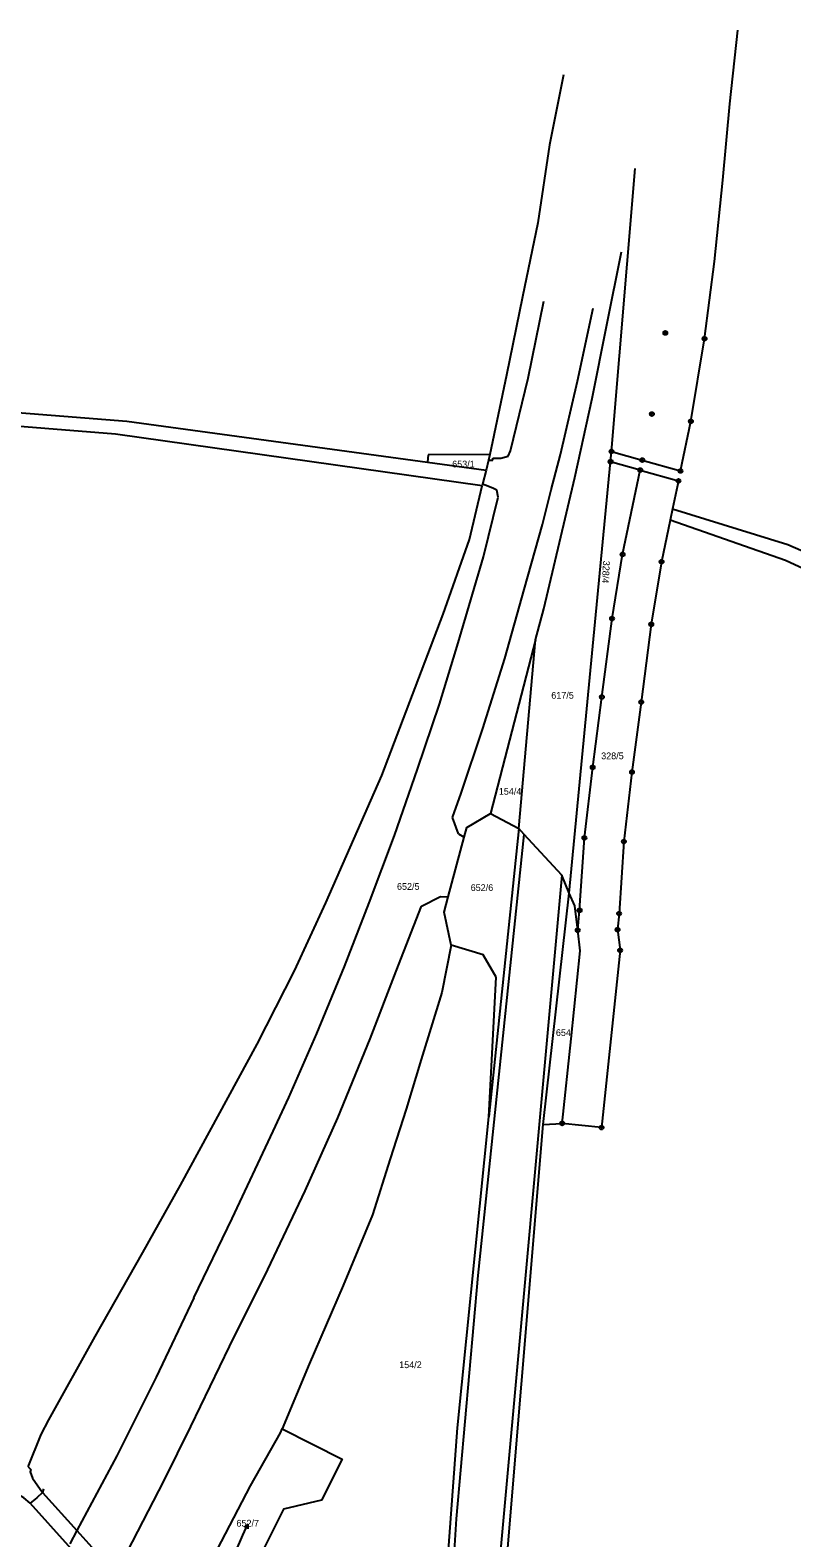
# Model space of a CAD drawing. Extents: x -783948 to -781889, y -1005870 to -1004430.
# Drawn here: x -783066.7 to -782874.5, y -1004810.4 to -1004430 of the extents above; entities that cross this region are included whole.
import ezdxf

# ---------------------------------------------------------------- set-up
doc = ezdxf.new("R2010")
doc.units = 0
for name, color, linetype in [('Vrstva 1', 7, 'Continuous'), ('Vrstva 2', 7, 'Continuous'), ('Vrstva 4', 7, 'Continuous'), ('Vrstva 7', 7, 'Continuous'), ('Vrstva 8', 7, 'Continuous')]:
    doc.layers.add(name, color=color, linetype=linetype)

msp = doc.modelspace()

# ---------------------------------------------------------------- linework, layer by layer
at = {"layer": 'Vrstva 1'}
for p, q in [((-782919.98, -1004536.27), (-782914.02, -1004464.87)), ((-782966.25, -1004537.12), (-782966.43, -1004538.99)), ((-782966.43, -1004538.99), (-782951.63, -1004541.02)), ((-782950.65, -1004537.03), (-782966.25, -1004537.12)), ((-782930.64, -1004647.72), (-782920.21, -1004538.85)), ((-782920.21, -1004538.85), (-782919.98, -1004536.27)), ((-782912.74, -1004540.96), (-782920.21, -1004538.85)), ((-782919.98, -1004536.27), (-782912.22, -1004538.46)), ((-782912.74, -1004540.96), (-782903.1, -1004543.69)), ((-782955.84, -1004558.52), (-782952.59, -1004544.91)), ((-782903.1, -1004543.69), (-782904.56, -1004550.71)), ((-782904.56, -1004550.71), (-782905.17, -1004553.62)), ((-782905.17, -1004553.62), (-782907.36, -1004564.1)), ((-782939.16, -1004583.81), (-782937.08, -1004575.97)), ((-782939.16, -1004583.81), (-782950.52, -1004627.63)), ((-782943.41, -1004631.44), (-782939.16, -1004583.81)), ((-782950.52, -1004627.63), (-782943.41, -1004631.44)), ((-782943.41, -1004631.44), (-782950.94, -1004704.2)), ((-782937.24, -1004706.12), (-782930.64, -1004647.72)), ((-782929.28, -1004650.94), (-782930.64, -1004647.72)), ((-782928.52, -1004657.08), (-782929.28, -1004650.94)), ((-782950.94, -1004704.2), (-782949.09, -1004668.94)), ((-782937.24, -1004706.12), (-782932.44, -1004705.83))]:
    msp.add_line(p, q, dxfattribs=at)
for points in [[(-782912.22, -1004538.46), (-782902.58, -1004541.19), (-782899.97, -1004528.67), (-782896.52, -1004507.82), (-782894, -1004488.33), (-782891.9, -1004467.84), (-782890.11, -1004448.58), (-782888.09, -1004429.95)], [(-782932.1, -1004441.24), (-782935.62, -1004458.85), (-782938.62, -1004478.6), (-782942.47, -1004497.23), (-782946.46, -1004517), (-782950.65, -1004537.03)], [(-782937.08, -1004575.97), (-782933.11, -1004559.26), (-782929.22, -1004542.81), (-782924.88, -1004522.91), (-782921.19, -1004504.35), (-782917.43, -1004485.86)], [(-782952.59, -1004544.91), (-783045.16, -1004531.87), (-783194.17, -1004519.95), (-783214.2, -1004520.81), (-783251.02, -1004519.09)], [(-783142, -1004520.7), (-783042.27, -1004528.59), (-782966.43, -1004538.99)], [(-782950.65, -1004537.03), (-782951.01, -1004538.49), (-782951.63, -1004541.02)], [(-782951.63, -1004541.02), (-782952.5, -1004544.55), (-782952.59, -1004544.91)], [(-782928.52, -1004657.08), (-782928.04, -1004652.07), (-782926.83, -1004633.8), (-782924.74, -1004615.97), (-782922.41, -1004598.24), (-782919.85, -1004578.44), (-782917.19, -1004562.27), (-782912.74, -1004540.96)], [(-782904.56, -1004550.71), (-782875.46, -1004559.76), (-782809.9, -1004588.39)], [(-782430.34, -1004673.42), (-782440.81, -1004671.9), (-782506.88, -1004656.53), (-782532.47, -1004648.66), (-782552.87, -1004641.62), (-782611, -1004618.35), (-782660.1, -1004608.13), (-782699.65, -1004606.49), (-782716.76, -1004604.99), (-782744.66, -1004601.77), (-782777.18, -1004599.46), (-782781.14, -1004603.06), (-782803.24, -1004595.16), (-782813.97, -1004592.59), (-782876.12, -1004563.82), (-782905.17, -1004553.62)], [(-783067.21, -1004792.53), (-783063.9, -1004784.36), (-783061.96, -1004780.66), (-783050.23, -1004759.6), (-783038.28, -1004738.39), (-783028.73, -1004721.42), (-783009.37, -1004685.85), (-782999.99, -1004667.33), (-782992.05, -1004650.2), (-782977.93, -1004618.08), (-782962.45, -1004577.29), (-782955.84, -1004558.52)], [(-782907.36, -1004564.1), (-782909.95, -1004579.89), (-782912.49, -1004599.53), (-782914.82, -1004617.2), (-782916.87, -1004634.71), (-782918.07, -1004652.88), (-782918.46, -1004656.94), (-782917.82, -1004662.16), (-782922.5, -1004706.89), (-782932.44, -1004705.83)], [(-782960.43, -1004660.85), (-782962.22, -1004652.56), (-782961.18, -1004648.66), (-782957.17, -1004633.59), (-782956.53, -1004631.17), (-782950.52, -1004627.63)], [(-782930.64, -1004647.72), (-782932.55, -1004643.22), (-782942.06, -1004632.9), (-782943.41, -1004631.44)], [(-782932.44, -1004705.83), (-782930.18, -1004684.52), (-782927.88, -1004662.26), (-782928.52, -1004657.08)], [(-782960.43, -1004660.85), (-782962.84, -1004672.8), (-782967.98, -1004689.74), (-782971.83, -1004702.21), (-782975.87, -1004714.79), (-782980.33, -1004728.92), (-782987.69, -1004746.79), (-782996.28, -1004766.56), (-783003.08, -1004782.88)], [(-782949.09, -1004668.94), (-782952.37, -1004663.28), (-782960.43, -1004660.85)], [(-782956.67, -1004889.51), (-782962.92, -1004837.52), (-782958.83, -1004782.65), (-782950.94, -1004704.2)], [(-782939.66, -1004916.37), (-782948.15, -1004837.18), (-782937.24, -1004706.12)], [(-783022.59, -1004819.39), (-783011.04, -1004797.27), (-783003.51, -1004783.92), (-783003.08, -1004782.88)], [(-783003.08, -1004782.88), (-782987.94, -1004790.58), (-782993.19, -1004800.96), (-783002.72, -1004803.18), (-783013.97, -1004825.57), (-783014.78, -1004835.49), (-783010.96, -1004843.13), (-782997.49, -1004858.4), (-782973.32, -1004885.78), (-782965.52, -1004890.41), (-782958.48, -1004890.63)], [(-783067.21, -1004792.53), (-783066.53, -1004793.18), (-783066.65, -1004793.77), (-783066.08, -1004795.34), (-783063.58, -1004798.99)], [(-783066.67, -1004801.71), (-783068.29, -1004800.32), (-783069.64, -1004799.61), (-783070.08, -1004799.63)], [(-783038.61, -1004832.85), (-783047.13, -1004823.4), (-783056.97, -1004812.48), (-783066.67, -1004801.71)], [(-783063.58, -1004798.99), (-783054.9, -1004808.6), (-783045.07, -1004819.49), (-783035.53, -1004830.06)]]:
    msp.add_lwpolyline(points, dxfattribs=at)
at = {"layer": 'Vrstva 4'}
for p, q in [((-782941.04, -1004517.81), (-782937.05, -1004498.37)), ((-782928.58, -1004518.52), (-782924.6, -1004500.1)), ((-782945.46, -1004536.15), (-782941.04, -1004517.81)), ((-782932.9, -1004537.06), (-782928.58, -1004518.52)), ((-782951.01, -1004538.49), (-782949.97, -1004538.5)), ((-782949.97, -1004538), (-782947.94, -1004537.96)), ((-782949.97, -1004538.5), (-782949.97, -1004538)), ((-782947.94, -1004537.96), (-782946.07, -1004537.5)), ((-782946.07, -1004537.5), (-782945.46, -1004536.15)), ((-782935.19, -1004545.99), (-782932.9, -1004537.06)), ((-782951.58, -1004544.82), (-782952.5, -1004544.55)), ((-782949.73, -1004545.63), (-782951.58, -1004544.82)), ((-782948.94, -1004546), (-782949.73, -1004545.63)), ((-782948.58, -1004547.81), (-782948.94, -1004546)), ((-782937.42, -1004554.69), (-782935.19, -1004545.99)), ((-782952.27, -1004562.85), (-782948.58, -1004547.81)), ((-782942, -1004571.14), (-782937.42, -1004554.69)), ((-782958.65, -1004584.59), (-782952.27, -1004562.85)), ((-782946.9, -1004588.48), (-782942, -1004571.14)), ((-782963.35, -1004600.08), (-782958.65, -1004584.59)), ((-782952.49, -1004606.16), (-782946.9, -1004588.48)), ((-782968.92, -1004616.45), (-782963.35, -1004600.08)), ((-782957.91, -1004622.52), (-782952.49, -1004606.16)), ((-782974.74, -1004633.17), (-782968.92, -1004616.45)), ((-782960.1, -1004628.61), (-782957.91, -1004622.52)), ((-782958.6, -1004632.78), (-782960.1, -1004628.61)), ((-782981.14, -1004650.17), (-782974.74, -1004633.17)), ((-782958.6, -1004632.78), (-782957.17, -1004633.59)), ((-782953.6, -1004744.25), (-782942.06, -1004632.9)), ((-782932.55, -1004643.22), (-782950.23, -1004838.1)), ((-782967.94, -1004651), (-782963.16, -1004648.62)), ((-782963.16, -1004648.62), (-782961.18, -1004648.66)), ((-782987.34, -1004666.25), (-782981.14, -1004650.17)), ((-782974.34, -1004667.4), (-782967.94, -1004651)), ((-782994.37, -1004683.12), (-782987.34, -1004666.25)), ((-782980.86, -1004684.51), (-782974.34, -1004667.4)), ((-783001.39, -1004699.34), (-782994.37, -1004683.12)), ((-782989.01, -1004704.45), (-782980.86, -1004684.51)), ((-783005.36, -1004707.79), (-783001.39, -1004699.34)), ((-782997.28, -1004722.87), (-782989.01, -1004704.45)), ((-783015.68, -1004729.83), (-783005.36, -1004707.79)), ((-783006.7, -1004742.68), (-782997.28, -1004722.87)), ((-783025.36, -1004749.87), (-783015.68, -1004729.83)), ((-783016.38, -1004762.16), (-783006.7, -1004742.68)), ((-782959.06, -1004805.66), (-782953.6, -1004744.25)), ((-783025.36, -1004749.87), (-783034.89, -1004769.91)), ((-783026.15, -1004782.3), (-783016.38, -1004762.16)), ((-783034.89, -1004769.91), (-783044.82, -1004789.73)), ((-783032.85, -1004795.97), (-783026.15, -1004782.3)), ((-783044.82, -1004789.73), (-783054.9, -1004808.6)), ((-783063.32, -1004798.02), (-783063.58, -1004798.99)), ((-783045.07, -1004819.49), (-783032.85, -1004795.97)), ((-783064.96, -1004800.36), (-783066.67, -1004801.71)), ((-783063.58, -1004798.99), (-783064.96, -1004800.36)), ((-782961.26, -1004837.87), (-782959.06, -1004805.66)), ((-783054.9, -1004808.6), (-783056.68, -1004811.93))]:
    msp.add_line(p, q, dxfattribs=at)
at = {"layer": 'Vrstva 7'}
for p, q in [((-783013.01, -1004809.75), (-783011.79, -1004807.01)), ((-783011.79, -1004807.01), (-783012.65, -1004807.72)), ((-783011.79, -1004807.01), (-783011.74, -1004808.13)), ((-783014.9, -1004814.01), (-783013.01, -1004809.75))]:
    msp.add_line(p, q, dxfattribs=at)
at = {"layer": 'Vrstva 8'}
for centre, radius in [((-782906.41, -1004506.36), 0.5), ((-782906.41, -1004506.36), 0.0303), ((-782896.52, -1004507.82), 0.5), ((-782896.52, -1004507.82), 0.0303), ((-782909.8, -1004526.83), 0.5), ((-782909.8, -1004526.83), 0.0303), ((-782899.97, -1004528.67), 0.5), ((-782899.97, -1004528.67), 0.0303), ((-782920.21, -1004538.85), 0.5), ((-782919.98, -1004536.27), 0.5), ((-782920.21, -1004538.85), 0.0303), ((-782919.98, -1004536.27), 0.0303), ((-782912.22, -1004538.46), 0.5), ((-782912.22, -1004538.46), 0.0303), ((-782912.74, -1004540.96), 0.5), ((-782912.74, -1004540.96), 0.0303), ((-782902.58, -1004541.19), 0.5), ((-782902.58, -1004541.19), 0.0303), ((-782903.1, -1004543.69), 0.5), ((-782903.1, -1004543.69), 0.0303), ((-782917.19, -1004562.27), 0.5), ((-782917.19, -1004562.27), 0.0303), ((-782907.36, -1004564.1), 0.5), ((-782907.36, -1004564.1), 0.0303), ((-782919.85, -1004578.44), 0.5), ((-782919.85, -1004578.44), 0.0303), ((-782909.95, -1004579.89), 0.5), ((-782909.95, -1004579.89), 0.0303), ((-782922.41, -1004598.24), 0.5), ((-782922.41, -1004598.24), 0.0303), ((-782912.49, -1004599.53), 0.5), ((-782912.49, -1004599.53), 0.0303), ((-782924.74, -1004615.97), 0.5), ((-782924.74, -1004615.97), 0.0303), ((-782914.82, -1004617.2), 0.5), ((-782914.82, -1004617.2), 0.0303), ((-782926.83, -1004633.8), 0.5), ((-782926.83, -1004633.8), 0.0303), ((-782916.87, -1004634.71), 0.5), ((-782916.87, -1004634.71), 0.0303), ((-782928.04, -1004652.07), 0.5), ((-782928.04, -1004652.07), 0.0303), ((-782918.07, -1004652.88), 0.5), ((-782918.07, -1004652.88), 0.0303), ((-782928.52, -1004657.08), 0.5), ((-782928.52, -1004657.08), 0.0303), ((-782918.46, -1004656.94), 0.5), ((-782918.46, -1004656.94), 0.0303), ((-782917.82, -1004662.16), 0.5), ((-782917.82, -1004662.16), 0.0303), ((-782932.44, -1004705.83), 0.5), ((-782932.44, -1004705.83), 0.0303), ((-782922.5, -1004706.89), 0.5), ((-782922.5, -1004706.89), 0.0303)]:
    msp.add_circle(centre, radius, dxfattribs=at)

# ---------------------------------------------------------------- texts
at = {"layer": 'Vrstva 2'}
for s, p in [('653/1', (-782960.19, -1004540.31)), ('617/5', (-782935.19, -1004598.67)), ('328/5', (-782922.6, -1004613.94)), ('154/4', (-782948.42, -1004622.9)), ('652/5', (-782974.12, -1004646.9)), ('652/6', (-782955.52, -1004647.19)), ('654', (-782934.02, -1004683.78)), ('154/2', (-782973.56, -1004767.6)), ('652/7', (-783014.62, -1004807.59))]:
    msp.add_text(s, height=1.7, dxfattribs=at).set_placement(p)
msp.add_text('328/4', height=1.7, rotation=267, dxfattribs=at).set_placement((-782922.1, -1004563.81))

doc.saveas('drawing.dxf')
